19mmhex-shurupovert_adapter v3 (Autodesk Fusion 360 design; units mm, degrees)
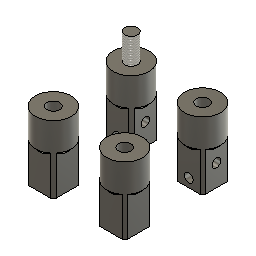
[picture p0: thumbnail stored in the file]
sketch "Sketch1" plane through (0, 0, 0) normal (0, 1, 0) x axis (1, 0, 0)
  line L1 (13, 0) -> (0, 0)
  line L2 (13, -13) -> (13, 0)
  line L3 (0, -13) -> (13, -13)
  line L4 (0, 0) -> (0, -13)
  point P1 (0, 0)
  point P2 (0, 0)
  point P6 (0, 0)
  point P3 (13, 0)
  point P4 (13, -13)
  coincident P1 P2
  horizontal L1
  perpendicular L1 L2
  perpendicular L2 L3
  coincident P1 P6
  perpendicular L1 L4
  dimension "d1" distance P2 P3 = 13
  dimension "d2" distance P3 P4 = 13
extrude "Extrude1" new body sketch "Sketch1" along normal blind 16
sketch "Sketch2" plane through (0, 16, 0) normal (0, 1, 0) x axis (-1, 0, 0)
  line L1 (-13, 13) -> (0, 13)
  line L2 (-13, 0) -> (-13, 13)
  line L3 (0, 0) -> (-13, 0)
  line L4 (0, 13) -> (0, 0)
  circle C1 centre (-6.5, 6.5) radius 8.25
  dimension "d6" diameter C1 = 16.5
extrude "Extrude2" cut sketch "Sketch2" against normal blind 16
extrude "Extrude3" add sketch "Sketch2" along normal blind 15
chamfer "Chamfer1" distance 2 distance 1.745
sketch "Sketch3" plane through (0, 31, 0) normal (0, 1, 0) x axis (-1, 0, 0)
  circle C1 centre (-6.5, 6.5) radius 8.25
  circle C2 centre (-6.5, 6.5) radius 2.9
  concentric C1 C2
  dimension "d13" diameter C2 = 5.8
extrude "Extrude4" cut sketch "Sketch3" profile of C2 against normal blind 18
sketch "Sketch4" plane through (0, 0, 0) normal (0, 0, -1) x axis (-1, 0, 0)
  line L1 (-1.4194, 18) -> (-1.4194, 0)
  curve K1 (-6.245, 16) -> (-1.4194, 18)
  line L2 (-6.755, 16) -> (-6.245, 16)
  curve K2 (-11.5806, 18) -> (-6.755, 16)
  line L3 (-11.5806, 0) -> (-11.5806, 18)
  line L4 (-1.4194, 0) -> (-11.5806, 0)
  line L5 (-6.5, 16) -> (-6.5, 0)
  line L6 (-6.5, 0) -> (-6.5, 8)
  circle C1 centre (-6.5, 4) radius 2
  point P8 (-6.5, 0)
  point P10 (-6.5, 8)
  point P11 (-6.5, 4)
  point P9 (-6.5, 16)
  midpoint L4 P8
  perpendicular L4 L5
  midpoint L5 P10
  midpoint L6 P11
  dimension "d16" distance P8 P9 = 16
  dimension "d17" diameter C1 = 4
sketch "Sketch5" plane through (0, 0, 13) normal (0, 0, 1) x axis (1, 0, 0)
  line L1 (11.5806, 18) -> (11.5806, 0)
  curve K1 (6.755, 16) -> (11.5806, 18)
  line L2 (6.245, 16) -> (6.755, 16)
  curve K2 (1.4194, 18) -> (6.245, 16)
  line L3 (1.4194, 0) -> (1.4194, 18)
  line L4 (11.5806, 0) -> (1.4194, 0)
  circle C1 centre (6.5, 4) radius 2
extrude "Extrude8" cut sketch "Sketch5" profile of C1 against normal blind 5
sketch "Sketch6" plane through (13, 0, 0) normal (1, 0, 0) x axis (0, 0, -1)
  line L1 (-1.4194, 18) -> (-1.4194, 0)
  curve K1 (-6.245, 16) -> (-1.4194, 18)
  line L2 (-6.755, 16) -> (-6.245, 16)
  curve K2 (-11.5806, 18) -> (-6.755, 16)
  line L3 (-11.5806, 0) -> (-11.5806, 18)
  line L4 (-1.4194, 0) -> (-11.5806, 0)
  line L5 (-6.5, 16) -> (-6.5, 0)
  line L6 (0, 6) -> (0, 2)
  line L7 (-13, 2) -> (-13, 6)
  line L8 (-13, 6) -> (0, 6)
  line L9 (-6.5, 8) -> (-6.5, 6)
  line L10 (-6.5, 12) -> (-6.5, 8)
  circle C1 centre (-6.5, 10) radius 2
  point P8 (-6.5, 0)
  point P11 (0, 6)
  point P14 (0, 6)
  point P12 (-13, 6)
  point P15 (-13, 6)
  point P16 (-6.5, 6)
  point P19 (-6.5, 10)
  point P18 (-6.5, 12)
  point P9 (-6.5, 16)
  point P17 (-6.5, 8)
  midpoint L4 P8
  perpendicular L4 L5
  coincident P11 P14
  coincident P12 P15
  midpoint L8 P16
  perpendicular L8 L9
  perpendicular L8 L10
  midpoint L10 P19
  coincident P18 C1
  dimension "d18" distance P8 P9 = 16
  dimension "d19" distance P16 P17 = 2
  dimension "d20" distance P17 P18 = 4
sketch "Sketch7" plane through (0, 0, 0) normal (-1, 0, 0) x axis (0, 0, 1)
  line L1 (1.4194, 0) -> (1.4194, 18)
  line L2 (11.5806, 0) -> (1.4194, 0)
  line L3 (11.5806, 18) -> (11.5806, 0)
  curve K1 (6.755, 16) -> (11.5806, 18)
  line L4 (6.245, 16) -> (6.755, 16)
  curve K2 (1.4194, 18) -> (6.245, 16)
  circle C1 centre (6.5, 10) radius 2
extrude "Extrude5" cut sketch "Sketch7" profile of C1 against normal blind 5
extrude "Extrude6" cut sketch "Sketch6" profile of L5 L10 C1 against normal blind 5
extrude "Extrude7" cut sketch "Sketch4" profile of L5 L6 C1 against normal blind 5
extrude "Extrude9" new body of existing geometry blind 30 bodies "m.bolt_m6"
thread "Thread1"
copy_paste_bodies "CopyPasteBodies1"
move "Move1"
extrude "Extrude10" add of existing geometry blind 5
extrude "Extrude11" add of existing geometry blind 5
extrude "Extrude12" add of existing geometry blind 5
extrude "Extrude13" add of existing geometry blind 5
copy_paste_bodies "CopyPasteBodies2"
move "Move2"
sketch "Sketch8" plane through (0, 0, 13) normal (0, 0, 1) x axis (1, 0, 0)
  line L1 (44.5806, 18) -> (44.5806, 0)
  curve K1 (39.755, 16) -> (44.5806, 18)
  line L2 (39.245, 16) -> (39.755, 16)
  curve K2 (34.4194, 18) -> (39.245, 16)
  line L3 (34.4194, 0) -> (34.4194, 18)
  line L4 (44.5806, 0) -> (34.4194, 0)
  line L5 (29, 18) -> (34.4194, 18)
  line L6 (29, -4) -> (29, 18)
  line L7 (48, 18) -> (34.4194, 18)
  line L8 (48, -4) -> (48, 18)
  line L9 (29, -4) -> (48, -4)
  circle C1 centre (39.5, 4) radius 2
  point P7 (34.4194, 18)
  point P9 (34.4194, 18)
  coincident P7 P9
  perpendicular L3 L5
  perpendicular L5 L6
  perpendicular L3 L7
  perpendicular L7 L8
  perpendicular L6 L9
extrude "Extrude14" cut sketch "Sketch8" against normal blind 0.1
extrude "Extrude15" cut of existing geometry blind -0.1
extrude "Extrude16" cut of existing geometry blind -0.1
extrude "Extrude17" cut of existing geometry blind -0.1
extrude "Extrude18" cut of existing geometry blind -2
extrude "Extrude19" cut of existing geometry blind -3
extrude "Extrude20" cut of existing geometry blind -1
extrude "Extrude21" cut of existing geometry blind -1
extrude "Extrude22" cut of existing geometry blind -1
extrude "Extrude23" cut of existing geometry blind -1
fillet "Fillet1" radius 7
fillet "Fillet2" radius 7
fillet "Fillet3" radius 7
fillet "Fillet4" radius 7
fillet "Fillet5" radius 6
move "Move3"
move "Move4"
copy_paste_bodies "CopyPasteBodies3"
move "Move5"
extrude "Extrude24" add of existing geometry blind 4.9
extrude "Extrude25" add of existing geometry blind 4.9
extrude "Extrude26" add of existing geometry blind 4.9
extrude "Extrude27" add of existing geometry blind 4.9
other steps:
base_feature "Base Feature1" bodies "19hex_adapter"
base_feature "Base Feature2" bodies "19hex_adapter (1)"
base_feature "Base Feature3" bodies "19hex_adapter(12.8)"
named bodies: "m.bolt_m6", "19hex_adapter", "19hex_adapter (1)", "19hex_adapter(12.8)"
